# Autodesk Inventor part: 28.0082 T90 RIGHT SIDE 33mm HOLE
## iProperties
Created: 2007-04
Part Number: 28.0082 T90 RIGHT SIDE 33mm HOLE
Document SubType Name: Modeling
Designer: Andy Moles
Material: Aluminum-6061
Density: 2.71 g/cm^3
Author: Andy Moles
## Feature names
1. Extrusion1
2. Chamfer1
3. Hole1
4. Hole2
5. Hole3
6. Hole4
7. Hole5
8. Extrusion2
9. Extrusion3
10. Hole6
11. Extrusion4
12. Hole7
13. Hole8
14. Hole9
15. Hole10
